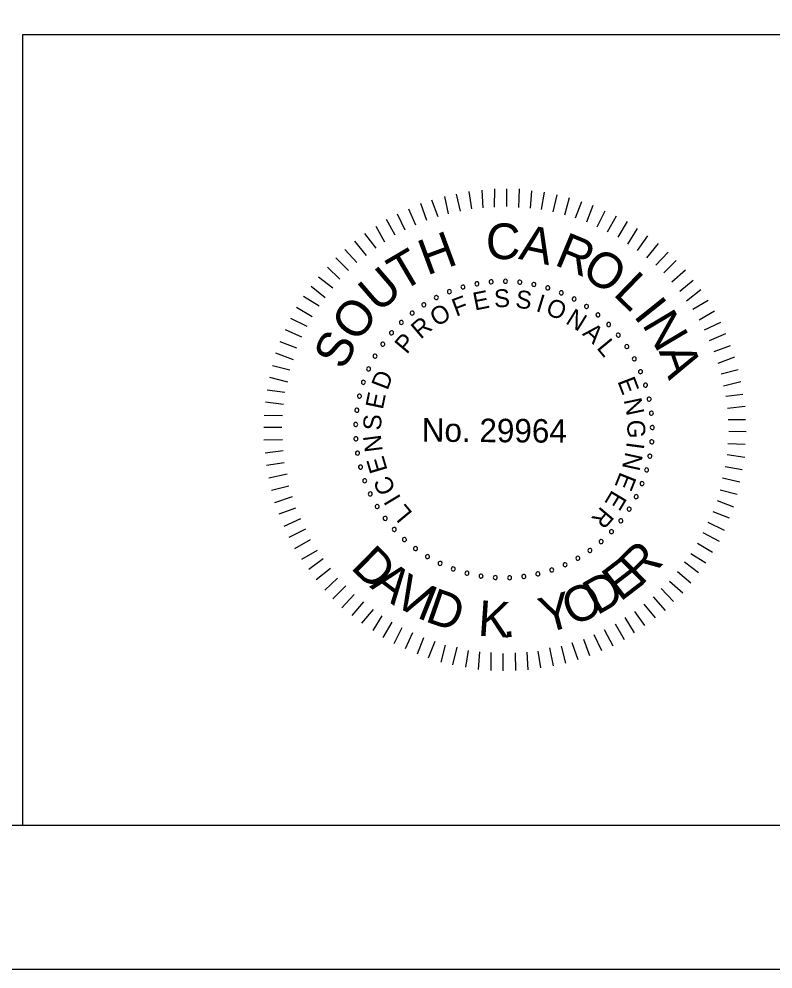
# Model space of a CAD drawing. Extents: x -133.1 to -97, y -1.7 to 20.3.
# Drawn here: x -110.52 to -107.898, y -1.691 to 1.613 of the extents above; entities that cross this region are included whole.
import ezdxf

# ---------------------------------------------------------------- set-up
doc = ezdxf.new("R2010")
doc.units = 0
for name, color, linetype in [('BR_BORDER LINES', 7, 'Continuous'), ('BR_TEXT', 7, 'Continuous'), ('Level 31', 7, 'Continuous')]:
    doc.layers.add(name, color=color, linetype=linetype)

msp = doc.modelspace()

# ---------------------------------------------------------------- linework, layer by layer
at = {"layer": 'BR_BORDER LINES'}
for p, q in [((-110.5071, 1.5591), (-105.1419, 1.5591)), ((-110.5071, -1.191), (-110.5071, 1.5591)), ((-131.3076, -1.191), (-97.6416, -1.191))]:
    msp.add_line(p, q, dxfattribs=at)
at = {"layer": 'BR_TEXT'}
for p, q in [((-109.0262, 0.9348), (-109.0394, 0.9958)), ((-108.9849, 0.9447), (-108.999, 1.0041)), ((-108.9454, 0.9521), (-108.9543, 1.0131)), ((-108.9059, 0.9561), (-108.9097, 1.017)), ((-108.8664, 0.9584), (-108.8658, 1.0227)), ((-108.8243, 0.9606), (-108.8238, 1.0224)), ((-108.7823, 0.9577), (-108.78, 1.022)), ((-108.742, 0.9548), (-108.7372, 1.0156)), ((-108.7034, 0.9501), (-108.6926, 1.011)), ((-108.6631, 0.9421), (-108.6489, 1.0012)), ((-108.622, 0.9314), (-108.606, 0.9922)), ((-109.1019, 0.9122), (-109.1229, 0.9708)), ((-109.0623, 0.9248), (-109.0842, 0.9824)), ((-108.5852, 0.9208), (-108.5633, 0.9781)), ((-108.5458, 0.9076), (-108.5239, 0.9658)), ((-109.1777, 0.8785), (-109.2039, 0.9345)), ((-109.1406, 0.8954), (-109.1642, 0.9514)), ((-108.5099, 0.8902), (-108.482, 0.9457)), ((-108.474, 0.8727), (-108.4427, 0.9282)), ((-109.2122, 0.8608), (-109.2426, 0.9151)), ((-108.4364, 0.8544), (-108.4042, 0.9082)), ((-109.2786, 0.8159), (-109.3177, 0.8668)), ((-109.2475, 0.8371), (-109.278, 0.8914)), ((-108.4031, 0.8301), (-108.3692, 0.8839)), ((-109.3123, 0.7904), (-109.3522, 0.8405)), ((-108.3699, 0.8083), (-108.3334, 0.8587)), ((-108.3375, 0.7824), (-108.2968, 0.8318)), ((-109.3451, 0.7658), (-109.3868, 0.8107)), ((-108.3059, 0.7572), (-108.2627, 0.8014)), ((-109.3745, 0.7386), (-109.4188, 0.7827)), ((-108.2779, 0.7295), (-108.2346, 0.7729)), ((-109.4039, 0.7079), (-109.4474, 0.7503)), ((-108.2498, 0.6984), (-108.2022, 0.74)), ((-109.4291, 0.6763), (-109.4786, 0.7154)), ((-108.2226, 0.6664), (-108.1759, 0.7046)), ((-109.4551, 0.6431), (-109.5046, 0.683)), ((-108.1988, 0.6327), (-108.1496, 0.6718)), ((-109.4768, 0.6141), (-109.5306, 0.6472)), ((-108.1768, 0.6034), (-108.1242, 0.6355)), ((-109.5012, 0.5774), (-109.5549, 0.6096)), ((-108.1548, 0.5663), (-108.1013, 0.5976)), ((-109.5186, 0.5432), (-109.575, 0.5711)), ((-109.5361, 0.5065), (-109.5933, 0.5318)), ((-108.137, 0.5318), (-108.0793, 0.5588)), ((-108.1193, 0.4948), (-108.0624, 0.5192)), ((-109.5536, 0.468), (-109.6117, 0.4899)), ((-108.1025, 0.456), (-108.0456, 0.477)), ((-109.5659, 0.4278), (-109.6275, 0.4506)), ((-108.0891, 0.4156), (-108.0314, 0.4374)), ((-109.5782, 0.3918), (-109.639, 0.4069)), ((-109.5854, 0.3498), (-109.6479, 0.3658)), ((-108.079, 0.3794), (-108.0189, 0.3935)), ((-108.0708, 0.3373), (-108.0106, 0.3522)), ((-109.596, 0.3138), (-109.6569, 0.3221)), ((-108.0625, 0.3012), (-108.0033, 0.3084)), ((-109.6006, 0.2727), (-109.6624, 0.2801)), ((-108.056, 0.26), (-107.995, 0.2663)), ((-109.6035, 0.2333), (-109.6679, 0.2338)), ((-108.0546, 0.2205), (-107.9945, 0.22)), ((-109.6056, 0.1921), (-109.6682, 0.1926)), ((-108.0524, 0.1793), (-107.9915, 0.1788)), ((-109.6042, 0.1492), (-109.6686, 0.148)), ((-108.0553, 0.1364), (-107.9952, 0.1342)), ((-109.602, 0.1105), (-109.6638, 0.1033)), ((-109.598, 0.0693), (-109.659, 0.0604)), ((-108.0574, 0.0978), (-107.9965, 0.0896)), ((-108.0645, 0.0566), (-108.0054, 0.0467)), ((-109.5881, 0.0297), (-109.6508, 0.0165)), ((-108.0735, 0.0172), (-108.0135, 0.003)), ((-109.5815, -0.0124), (-109.6426, -0.0265)), ((-108.0824, -0.0248), (-108.0224, -0.0398)), ((-109.5698, -0.0493), (-109.6318, -0.0703)), ((-108.093, -0.0615), (-108.0357, -0.0835)), ((-109.5582, -0.0881), (-109.6167, -0.1091)), ((-109.5413, -0.1251), (-109.599, -0.1521)), ((-108.107, -0.1001), (-108.0506, -0.122)), ((-109.5244, -0.1613), (-109.5813, -0.1909)), ((-108.1245, -0.1368), (-108.0681, -0.1647)), ((-108.1428, -0.1727), (-108.0856, -0.2032)), ((-109.5076, -0.1984), (-109.5619, -0.2297)), ((-108.1612, -0.2095), (-108.1082, -0.2417)), ((-109.4838, -0.2355), (-109.5382, -0.2668)), ((-108.1838, -0.2462), (-108.1317, -0.2784)), ((-109.4626, -0.2648), (-109.5127, -0.3013)), ((-108.2063, -0.2752), (-108.1577, -0.3125)), ((-109.4372, -0.2985), (-109.4873, -0.3376)), ((-108.2306, -0.3084), (-108.1846, -0.3483)), ((-109.4125, -0.3321), (-109.4567, -0.373)), ((-109.3836, -0.3582), (-109.4286, -0.4032)), ((-108.2583, -0.3417), (-108.2115, -0.3833)), ((-109.3547, -0.3884), (-109.3971, -0.4344)), ((-108.2869, -0.3672), (-108.2444, -0.413)), ((-109.3222, -0.4144), (-109.363, -0.4613)), ((-108.3474, -0.4225), (-108.3075, -0.47)), ((-108.3155, -0.397), (-108.273, -0.4437)), ((-109.289, -0.4404), (-109.3289, -0.4882)), ((-109.2583, -0.4622), (-109.2896, -0.5142)), ((-108.3802, -0.448), (-108.3446, -0.4963)), ((-109.2233, -0.4847), (-109.2546, -0.5386)), ((-108.4475, -0.4911), (-108.4162, -0.5455)), ((-108.4139, -0.4691), (-108.3808, -0.5217)), ((-109.1891, -0.5048), (-109.2162, -0.5603)), ((-109.1523, -0.5222), (-109.1769, -0.5778)), ((-108.5216, -0.5274), (-108.4947, -0.5835)), ((-108.4855, -0.5106), (-108.455, -0.5666)), ((-109.1139, -0.5397), (-109.1358, -0.5962)), ((-109.0745, -0.552), (-109.0973, -0.6102)), ((-108.5974, -0.556), (-108.5764, -0.6145)), ((-108.5578, -0.5443), (-108.5368, -0.6011)), ((-109.0386, -0.5644), (-109.0528, -0.6235)), ((-108.9974, -0.5716), (-109.0126, -0.6333)), ((-108.9581, -0.5831), (-108.968, -0.6413)), ((-108.9186, -0.5877), (-108.9234, -0.6494)), ((-108.8792, -0.5906), (-108.8797, -0.6524)), ((-108.8372, -0.5935), (-108.8377, -0.6544)), ((-108.7951, -0.5913), (-108.7939, -0.6531)), ((-108.7547, -0.589), (-108.7509, -0.6509)), ((-108.7161, -0.5851), (-108.7062, -0.6435)), ((-108.6756, -0.5742), (-108.6624, -0.6361)), ((-108.6344, -0.5677), (-108.6194, -0.627))]:
    msp.add_line(p, q, dxfattribs=at)
for centre, start, end in [((-108.9278, 0.692), 10.6038, 190.6038), ((-108.8784, 0.6987), 5.0653, 185.0653), ((-108.8784, 0.6987), 185.0653, 5.0653), ((-108.8286, 0.7006), 359.5268, 179.5268), ((-108.8286, 0.7006), 179.5268, 359.5268), ((-108.7789, 0.6977), 173.9884, 353.9884), ((-108.7789, 0.6977), 353.9884, 173.9884), ((-108.7296, 0.69), 348.4499, 168.4499), ((-109.0235, 0.6646), 21.6807, 201.6807), ((-109.0235, 0.6646), 201.6807, 21.6807), ((-108.9763, 0.6806), 16.1422, 196.1422), ((-108.9763, 0.6806), 196.1422, 16.1422), ((-108.9278, 0.692), 190.6038, 10.6038), ((-108.7296, 0.69), 168.4499, 348.4499), ((-108.6814, 0.6776), 162.9114, 342.9114), ((-108.6814, 0.6776), 342.9114, 162.9114), ((-108.6345, 0.6606), 157.373, 337.373), ((-108.6345, 0.6606), 337.373, 157.373), ((-109.0689, 0.644), 27.2191, 207.2191), ((-109.0689, 0.644), 207.2191, 27.2191), ((-108.5896, 0.6391), 151.8345, 331.8345), ((-108.5896, 0.6391), 331.8345, 151.8345), ((-109.1527, 0.5903), 38.2961, 218.2961), ((-109.1121, 0.6192), 32.7576, 212.7576), ((-109.1121, 0.6192), 212.7576, 32.7576), ((-108.5469, 0.6134), 146.2961, 326.2961), ((-108.5469, 0.6134), 326.2961, 146.2961), ((-109.1903, 0.5577), 43.8345, 223.8345), ((-109.1903, 0.5577), 223.8345, 43.8345), ((-109.1527, 0.5903), 218.2961, 38.2961), ((-108.5069, 0.5837), 140.7576, 320.7576), ((-108.5069, 0.5837), 320.7576, 140.7576), ((-108.4699, 0.5503), 135.2191, 315.2191), ((-108.4699, 0.5503), 315.2191, 135.2191), ((-109.2246, 0.5215), 49.373, 229.373), ((-109.2246, 0.5215), 229.373, 49.373), ((-108.4363, 0.5134), 129.6807, 309.6807), ((-108.4363, 0.5134), 309.6807, 129.6807), ((-109.2553, 0.4822), 54.9114, 234.9114), ((-109.2553, 0.4822), 234.9114, 54.9114), ((-108.4065, 0.4735), 124.1422, 304.1422), ((-108.4065, 0.4735), 304.1422, 124.1422), ((-109.282, 0.4402), 60.4499, 240.4499), ((-109.282, 0.4402), 240.4499, 60.4499), ((-108.3806, 0.4309), 118.6038, 298.6038), ((-108.3806, 0.4309), 298.6038, 118.6038), ((-109.3045, 0.3957), 65.9884, 245.9884), ((-109.3045, 0.3957), 245.9884, 65.9884), ((-108.359, 0.3861), 113.0653, 293.0653), ((-108.359, 0.3861), 293.0653, 113.0653), ((-109.3227, 0.3493), 71.5268, 251.5268), ((-109.3227, 0.3493), 251.5268, 71.5268), ((-108.3418, 0.3393), 107.5268, 287.5268), ((-108.3418, 0.3393), 287.5268, 107.5268), ((-109.3363, 0.3014), 77.0653, 257.0653), ((-109.3363, 0.3014), 257.0653, 77.0653), ((-108.3292, 0.2911), 101.9884, 281.9884), ((-108.3292, 0.2911), 281.9884, 101.9884), ((-109.3452, 0.2524), 82.6038, 262.6038), ((-109.3452, 0.2524), 262.6038, 82.6038), ((-108.3213, 0.2419), 96.4499, 276.4499), ((-108.3213, 0.2419), 276.4499, 96.4499), ((-109.3493, 0.2027), 88.1422, 268.1422), ((-109.3493, 0.2027), 268.1422, 88.1422), ((-108.3182, 0.1921), 90.9114, 270.9114), ((-108.3182, 0.1921), 270.9114, 90.9114), ((-109.3486, 0.1529), 93.6807, 273.6807), ((-109.3486, 0.1529), 273.6807, 93.6807), ((-108.3199, 0.1423), 85.373, 265.373), ((-108.3199, 0.1423), 265.373, 85.373), ((-109.3431, 0.1033), 99.2191, 279.2191), ((-109.3431, 0.1033), 279.2191, 99.2191), ((-108.3265, 0.0929), 79.8345, 259.8345), ((-108.3265, 0.0929), 259.8345, 79.8345), ((-109.3328, 0.0546), 104.7576, 284.7576), ((-109.3328, 0.0546), 284.7576, 104.7576), ((-108.3377, 0.0444), 74.2961, 254.2961), ((-108.3377, 0.0444), 254.2961, 74.2961), ((-109.3179, 0.007), 110.2961, 290.2961), ((-109.3179, 0.007), 290.2961, 110.2961), ((-108.3536, -0.0028), 68.7576, 248.7576), ((-108.3536, -0.0028), 248.7576, 68.7576), ((-109.2985, -0.0389), 115.8345, 295.8345), ((-109.2985, -0.0389), 295.8345, 115.8345), ((-108.374, -0.0483), 63.2191, 243.2191), ((-108.374, -0.0483), 243.2191, 63.2191), ((-109.2747, -0.0826), 121.373, 301.373), ((-109.2747, -0.0826), 301.373, 121.373), ((-108.3986, -0.0916), 57.6807, 237.6807), ((-108.3986, -0.0916), 237.6807, 57.6807), ((-109.2468, -0.1239), 126.9114, 306.9114), ((-109.2468, -0.1239), 306.9114, 126.9114), ((-108.4273, -0.1323), 52.1422, 232.1422), ((-108.4273, -0.1323), 232.1422, 52.1422), ((-109.2151, -0.1624), 132.4499, 312.4499), ((-109.2151, -0.1624), 312.4499, 132.4499), ((-108.4599, -0.1701), 46.6038, 226.6038), ((-108.4599, -0.1701), 226.6038, 46.6038), ((-109.1798, -0.1975), 137.9884, 317.9884), ((-109.1798, -0.1975), 317.9884, 137.9884), ((-108.4959, -0.2045), 41.0653, 221.0653), ((-109.1413, -0.2291), 143.5268, 323.5268), ((-109.1413, -0.2291), 323.5268, 143.5268), ((-108.5351, -0.2353), 35.5268, 215.5268), ((-108.5351, -0.2353), 215.5268, 35.5268), ((-108.4959, -0.2045), 221.0653, 41.0653), ((-109.0999, -0.2569), 149.0653, 329.0653), ((-109.0999, -0.2569), 329.0653, 149.0653), ((-108.577, -0.2622), 29.9884, 209.9884), ((-108.577, -0.2622), 209.9884, 29.9884), ((-109.056, -0.2805), 154.6038, 334.6038), ((-109.056, -0.2805), 334.6038, 154.6038), ((-109.01, -0.2997), 340.1422, 160.1422), ((-108.6677, -0.3032), 18.9114, 198.9114), ((-108.6214, -0.2849), 24.4499, 204.4499), ((-108.6214, -0.2849), 204.4499, 24.4499), ((-109.01, -0.2997), 160.1422, 340.1422), ((-108.9624, -0.3145), 165.6807, 345.6807), ((-108.9624, -0.3145), 345.6807, 165.6807), ((-108.9136, -0.3245), 171.2191, 351.2191), ((-108.9136, -0.3245), 351.2191, 171.2191), ((-108.8641, -0.3299), 356.7576, 176.7576), ((-108.8641, -0.3299), 176.7576, 356.7576), ((-108.8142, -0.3304), 2.2961, 182.2961), ((-108.8142, -0.3304), 182.2961, 2.2961), ((-108.7646, -0.3261), 7.8345, 187.8345), ((-108.7646, -0.3261), 187.8345, 7.8345), ((-108.7156, -0.317), 13.373, 193.373), ((-108.7156, -0.317), 193.373, 13.373), ((-108.6677, -0.3032), 198.9114, 18.9114)]:
    msp.add_arc(centre, 0.00701, start, end, dxfattribs=at)
at = {"layer": 'Level 31'}
msp.add_lwpolyline([(-133.1409, -1.691), (-97.141, -1.691), (-97.141, 20.309), (-133.1409, 20.309)], close=True, dxfattribs=at)

# ---------------------------------------------------------------- texts
at = {"layer": 'BR_TEXT'}
for s, height, rotation, p in [('C', 0.1241, 359.5482, (-108.8971, 0.7782)), ('H', 0.1241, 20.3637, (-109.1015, 0.7199)), ('A', 0.1241, 348.1981, (-108.7857, 0.779)), ('R', 0.1241, 337.4344, (-108.6624, 0.7591)), ('T', 0.1241, 30.4992, (-109.1894, 0.6624)), ('O', 0.1239, 326.5869, (-108.5702, 0.7224)), ('U', 0.1241, 40.8022, (-109.2706, 0.5876)), ('L', 0.1241, 315.9488, (-108.4576, 0.6546)), ('E', 0.0622, 11.4103, (-108.9351, 0.5987)), ('S', 0.0622, 2.208, (-108.8672, 0.6097)), ('S', 0.0622, 352.6608, (-108.796, 0.6095)), ('O', 0.1241, 52.0267, (-109.3451, 0.4837)), ('F', 0.0622, 20.6127, (-109.0002, 0.577)), ('I', 0.0622, 343.1136, (-108.7257, 0.5975)), ('O', 0.0622, 338.4392, (-108.6923, 0.5873)), ('I', 0.1241, 308.6613, (-108.3862, 0.5803)), ('O', 0.0622, 30.8477, (-109.0676, 0.541)), ('N', 0.0622, 328.2042, (-108.6227, 0.5559)), ('N', 0.1241, 300.7037, (-108.3556, 0.5509)), ('R', 0.0622, 40.3949, (-109.1237, 0.4971)), ('A', 0.0622, 318.657, (-108.5637, 0.5159)), ('S', 0.1239, 63.2511, (-109.3905, 0.3881)), ('P', 0.0622, 49.9421, (-109.1718, 0.4445)), ('L', 0.0622, 309.4546, (-108.5139, 0.4686)), ('A', 0.1241, 289.4792, (-108.2964, 0.4579)), ('D', 0.0622, 69.0364, (-109.2388, 0.3192)), ('E', 0.0622, 291.049, (-108.44, 0.3533)), ('E', 0.0622, 78.2388, (-109.2553, 0.2526)), ('N', 0.0622, 281.8466, (-108.4179, 0.2882)), ('S', 0.0622, 87.786, (-109.2611, 0.1815)), ('No. 29964', 0.08175, 359.5268, (-109.1199, 0.1431)), ('G', 0.0622, 272.2995, (-108.4061, 0.2179)), ('N', 0.0622, 97.3332, (-109.2549, 0.1105)), ('I', 0.0622, 262.4084, (-108.4065, 0.1441)), ('N', 0.0622, 257.7339, (-108.411, 0.1095)), ('E', 0.0622, 106.5355, (-109.2379, 0.044)), ('E', 0.0622, 248.1867, (-108.4291, 0.0406)), ('C', 0.0622, 116.4266, (-109.208, -0.0235)), ('E', 0.0622, 238.9844, (-108.457, -0.0222)), ('I', 0.0622, 121.1011, (-109.1899, -0.0534)), ('L', 0.0622, 129.9595, (-109.1493, -0.1056)), ('R', 0.0622, 229.782, (-108.4947, -0.0797)), ('D', 0.1236, 315.4053, (-109.3698, -0.2962)), ('R', 0.1236, 44.5947, (-108.3589, -0.3617)), ('E', 0.1236, 37.5339, (-108.4295, -0.4156)), ('A', 0.1236, 322.8377, (-109.3032, -0.3618)), ('V', 0.1236, 330.5179, (-109.226, -0.42)), ('D', 0.1236, 30.1015, (-108.5104, -0.4626)), ('I', 0.1236, 338.1981, (-109.1418, -0.4674)), ('O', 0.1236, 22.4212, (-108.5997, -0.4996)), ('D', 0.1236, 340.7995, (-109.1119, -0.4808)), ('Y', 0.1236, 14.8649, (-108.6915, -0.5241)), ('K', 0.1236, 356.098, (-108.9267, -0.5314)), ('.', 0.1236, 3.1588, (-108.838, -0.5377))]:
    msp.add_text(s, height=height, rotation=rotation, dxfattribs=at).set_placement(p)

doc.saveas('drawing.dxf')
